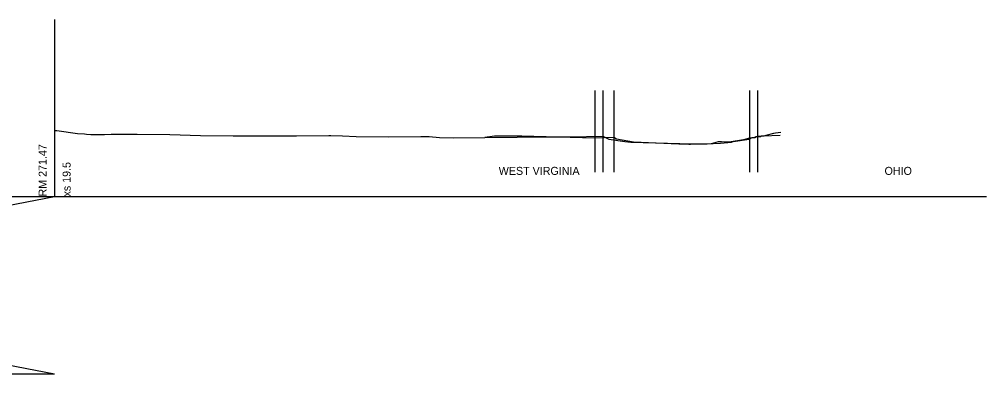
# Model space of a CAD drawing. Extents: x -9489 to 16720, y -4790 to 1662.
# Drawn here: x 7653 to 16720, y -4790 to -1466 of the extents above; entities that cross this region are included whole.
import ezdxf

# ---------------------------------------------------------------- set-up
doc = ezdxf.new("R2010")
doc.units = 0
for name, color, linetype in [('MD_P_Surface_Finished_Grade', 7, 'Continuous'), ('PF_P_Grade_Line', 7, 'Continuous'), ('PF_X_Ground_Line', 7, 'Continuous'), ('SC_Scratch1', 7, 'Continuous')]:
    doc.layers.add(name, color=color, linetype=linetype)

msp = doc.modelspace()

# ---------------------------------------------------------------- linework, layer by layer
at = {"layer": 'MD_P_Surface_Finished_Grade'}
for p, q in [((13122.7, -2134.8), (13122.7, -2898.7)), ((14570.7, -2134.8), (14570.7, -2898.7))]:
    msp.add_line(p, q, dxfattribs=at)
at = {"layer": 'PF_P_Grade_Line'}
for p, q in [((13048.7, -2134.8), (13048.7, -2898.7)), ((13226.4, -2134.8), (13226.4, -2898.7)), ((14498.1, -2134.8), (14498.1, -2898.7)), ((12106.5, -2563.6), (12014.7, -2574.2)), ((-752.6, -3128.2), (7983.7, -4790.1)), ((-752.6, -4790.1), (7983.7, -3128.2))]:
    msp.add_line(p, q, dxfattribs=at)
at = {"layer": 'PF_X_Ground_Line'}
msp.add_lwpolyline([(14600.2, -2568.8), (14596.7, -2567.7), (14593.7, -2567.4), (14579.4, -2567.2), (14564.8, -2567.4), (14553.2, -2568.6), (14552.9, -2572.2)], dxfattribs=at)
at = {"layer": 'SC_Scratch1'}
for points in [[(-752.6, -1466.4), (-752.6, -3128.2), (7983.7, -3128.2)], [(7983.7, -1466.4), (7983.7, -3128.2), (16719.9, -3128.2)], [(7983.7, -2509.2), (8004.7, -2508.7), (8196.7, -2538.2), (8262.7, -2541.2), (8281.7, -2544.2), (8322.7, -2545.2), (8414.7, -2545.7), (8433.7, -2546.2), (8449.7, -2547.2), (8513.7, -2544.2), (8528.7, -2543.7), (8548.7, -2543.8), (8758.7, -2543.7), (9062.7, -2545.2), (9351.7, -2557.2), (9656.7, -2559.7), (9952.7, -2560.2), (10251.7, -2560.2), (10552.7, -2557.2), (10571.7, -2556.7), (10681.7, -2557.7), (10811.7, -2565.7), (11114.7, -2567.2), (11416.7, -2566.2), (11494.7, -2565.2), (11591.7, -2575.7), (11720.7, -2577.2), (12014.7, -2574.2), (12320.7, -2570.2), (12519.7, -2569.2), (12813.7, -2568.7), (13122.7, -2561.2), (13179.7, -2589.2), (13329.2, -2612.2), (13383.7, -2618.2), (13958.7, -2633.2), (14088.7, -2634.2), (14223.7, -2628.2), (14328.7, -2618.2), (14343.2, -2612.2), (14492.7, -2589.2), (14521.7, -2576.2), (14548.7, -2576.2), (14570.7, -2561.2), (14587.7, -2561.2), (14623.7, -2560.2), (14783.7, -2553.2)], [(14790.1, -2528.2), (14741.2, -2533.6), (14721.6, -2537), (14649.3, -2555.5), (14630.9, -2562.2), (14619.6, -2562.3), (14609.2, -2563.7), (14599.5, -2569.2), (14595.3, -2568.3), (14593.7, -2567.8), (14579.4, -2567.4), (14564.8, -2568), (14557.4, -2570.3), (14552.9, -2572.2), (14543.3, -2576.1), (14498.1, -2579.8), (14440.7, -2595.7), (14324.4, -2615.7), (14299.5, -2617.3), (14233.3, -2614.5), (14204.3, -2617), (14136.3, -2633.8), (14099.4, -2636.8), (14058.3, -2635.8), (13943.7, -2639.3), (13926.8, -2639.2), (13833.1, -2636.7), (13409.8, -2617.7), (13249.9, -2590.3), (13226.4, -2575.9), (13044.4, -2580.2), (12362.7, -2562.1), (12106.5, -2563.6)], [(-752.6, -3128.2), (-752.6, -4790.1), (7983.7, -4790.1)]]:
    msp.add_lwpolyline(points, dxfattribs=at)

# ---------------------------------------------------------------- texts
at = {"layer": 'MD_P_Surface_Finished_Grade'}
for s, p in [('WEST VIRGINIA', (12146.4, -2925.3)), ('OHIO', (15762.9, -2925.3))]:
    msp.add_text(s, height=75, dxfattribs=at).set_placement(p)
at = {"layer": 'SC_Scratch1'}
for s, p in [('RM 271.47', (7908.7, -3128.2)), ('xs 19.5', (8133.7, -3128.2))]:
    msp.add_text(s, height=75, rotation=90, dxfattribs=at).set_placement(p)

doc.saveas('drawing.dxf')
